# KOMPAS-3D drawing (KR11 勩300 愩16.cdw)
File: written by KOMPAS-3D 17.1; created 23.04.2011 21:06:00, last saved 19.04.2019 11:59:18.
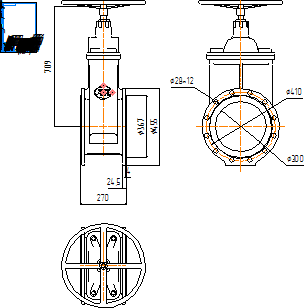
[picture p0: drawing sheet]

Sheet 1: A4, portrait

Title block, sheet 1: name: KR11 Ду300 Ру16; material: Внимание! Данный продукт является объектом авторского права ООО «Торговый Дом АДЛ». / Запрещается изменение, копирование, распространение / (в том числе путем копирования на другие сайты и ресурсы в Интернете) / или любое иное использование информации и объектов без предварительного / согласия правообладателя (ООО «Торговый Дом АДЛ»).; scale: 1:1; sheets: 1; organisation: ООО "Торговый дом АДЛ"; sheet format: A4; stored path: \\adlc.lan\data\АДЛ_ПКД\3D-модели\ADL production\Клиновые задвижки серии KR ГРАНАР\Клиновые задвижки KR11\KOMPAS 2D\KR11 Ду300 Ру16.cdw

Views: Спереди 4, Проекционный вид 5, Проекционный вид 6
Dimensions and other numbers on the sheet: 709; 270; 24,5; 4; 367; 455; 410; 28; 300; 1:1; 1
